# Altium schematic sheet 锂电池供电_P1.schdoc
size 297 x 209 mm; Symbol: Drawing-Symbol_A4; Company: 嘉立创EDA; Version: V1.0; Page Size: A4; @Project Name: 水墨屏demo1; @Update Date: 2026-03-01; @Create Date: 2026-03-01; Device: Drawing-Symbol_A4; @Board Name: Board1; @Page Name: P1; @Create Time: 22:34:30; @Page Count: 1; @Page No: 1; @Schematic Name: Schematic1; @Update Time: 22:34:30; @Assembly Variant: Basic; Border: 1; Title Block Position: 3; Size: A4; Width: 1170; Height: 825; Region Start: 1; X Region Count: 6; Y Region Count: 4; Blade Width: 10
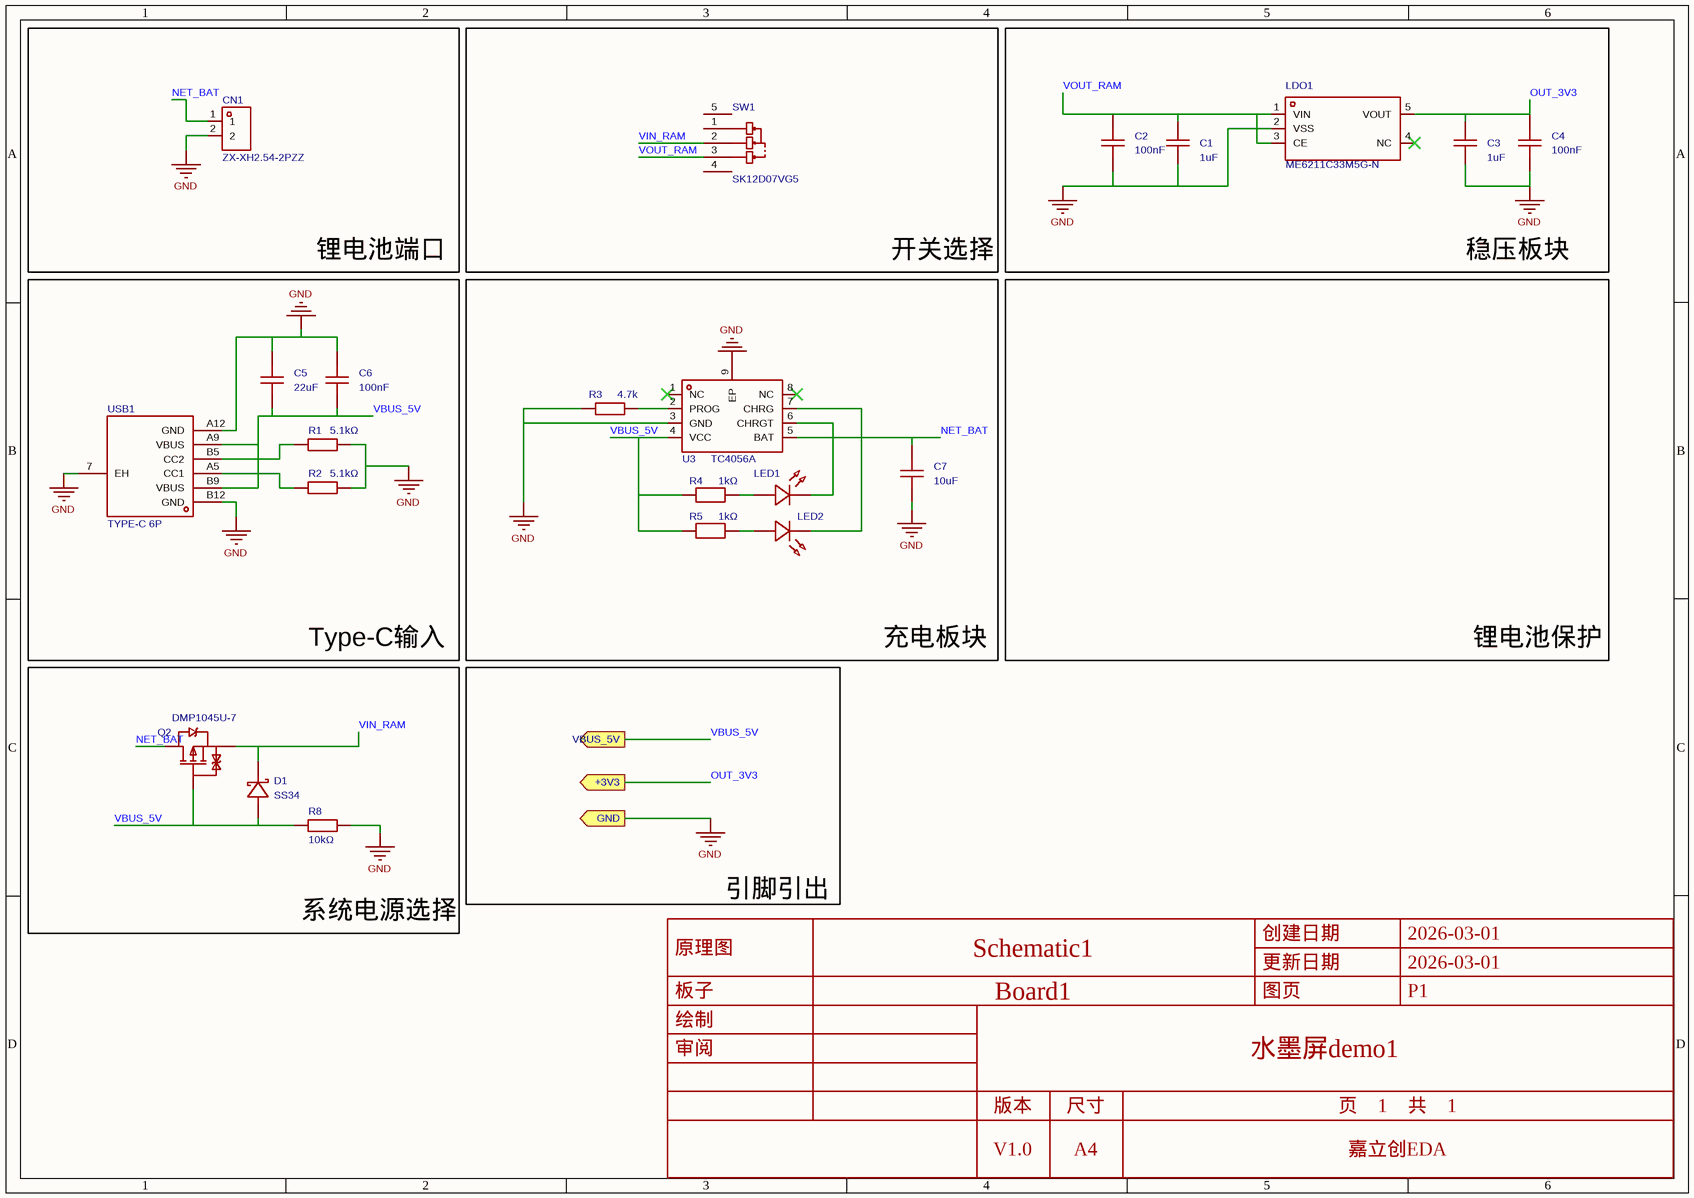
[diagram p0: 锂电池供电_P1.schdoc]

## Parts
C1  1uF  [C0603]
C2  100nF  [C0603]
C3  1uF  [C0603]
C4  100nF  [C0603]
C5  22uF  [C0603]
C6  100nF  [C0603]
C7  10uF  [C0603]
CN1  ZX-XH2.54-2PZZ  [CONN-TH_2P-P2.50_HX25003-2A]
D1  SS34  [SMA_L4.3-W2.6-LS5.0-FD]
LDO1  ME6211C33M5G-N  [SOT-23-5_L3.0-W1.7-P0.95-LS2.8-BL]
LED1  GL0603UR01  [LED0603-FD]  (value not drawn)
LED2  MHT192DUGCT  [LED0603-RD]  (value not drawn)
Q2  DMP1045U-7  [SOT-23-3_L2.9-W1.3-P1.90-LS2.4-BR]
R1  5.1kΩ  [R0603]
R2  5.1kΩ  [R0603]
R3  4.7k  [R0603]
R4  1kΩ  [R0603]
R5  1kΩ  [R0603]
R8  10kΩ  [R0603]
SW1  SK12D07VG5  [SW-TH_SK12D07VG5-1]
U3  TC4056A  [ESOP-8_L4.9-W3.9-P1.27-LS6.0-BL-EP]
USB1  TYPE-C 6P  [TYPE-C-SMD_TYPE-C-6P_1]

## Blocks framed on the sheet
锂电池端口: CN1
开关选择: SW1
稳压板块: C1-C4 LDO1
Type-C输入: C5 C6 R1 R2 USB1
充电板块: C7 LED1 LED2 R3-R5 U3

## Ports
+3V3 (out), GND (out), VBUS_5V (out)

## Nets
GND: C1.1 C2.1 C3.1 C4.1 C5.1 C6.2 C7.1 CN1.2 LDO1.2(VSS) R1.2 R2.2 R3.1 R8.2 U3.3(GND) U3.9(EP) USB1.7(EH) USB1.A12(GND) USB1.B12(GND) ; port GND
NET_BAT: C7.2 CN1.1 Q2.3(D) U3.5(BAT)
OUT_3V3: C3.2 C4.2 LDO1.5(VOUT) ; port +3V3
VBUS_5V: C5.2 C6.1 D1.1(A) Q2.1(G) R4.1 R5.1 R8.1 U3.4(VCC) USB1.A9(VBUS) USB1.B9(VBUS) ; port VBUS_5V
VIN_RAM: D1.2(K) Q2.2(S) SW1.2
VOUT_RAM: C1.2 C2.2 LDO1.1(VIN) LDO1.3(CE) SW1.3
NetLED1_1: LED1.1(A) R4.2
NetLED1_2: LED1.2(C) U3.6(CHRGT)
NetLED2_1: LED2.1(K) U3.7(CHRG)
NetLED2_2: LED2.2(A) R5.2
NetR1_1: R1.1 USB1.B5(CC2)
NetR2_1: R2.1 USB1.A5(CC1)
NetR3_2: R3.2 U3.2(PROG)

Not connected (* = marked no-connect by the designer): LDO1 4(NC)*; SW1 1 4 5; U3 1(NC)* 8(NC)*

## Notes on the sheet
- 锂电池保护
- 系统电源选择
- 引脚引出

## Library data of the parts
C1 C3 = CL10B105KQ8NNNC: 容值:1uF;精度:±10%;额定电压:6.3V;温度系数:X7R;; Manufacturer: SAMSUNG(三星); 3D Model: ac125912035d415993ca9572d50418b10819f05c4eef4c71ace90d822a990e87; 3D Model Transform: 62.992,31.496,0,0,0,0,0,0,0; Tolerance: ±10%; Voltage Rating: 6.3V; Temperature Coefficient: X7R; AddInBom: yes; ModelName: C0603_L1.6-W0.8-H0.8
C2 C4 C6 = CGA0603X7R104K500JT: 容值:100nF;精度:±10%;额定电压:50V;温度系数:X7R;; Manufacturer: HRE(芯声); 3D Model: ac125912035d415993ca9572d50418b1; 3D Model Transform: 62.992,31.496,0,0,0,0,0,0,0; Tolerance: ±10%; Voltage Rating: 50V; Temperature Coefficient: X7R; AddInBom: yes; ModelName: C0603_L1.6-W0.8-H0.8
C5 = 0603X226M6R3NT: 容值:22uF;精度:±20%;额定电压:6.3V;温度系数:X5R;; Manufacturer: FH(风华); 3D Model: ac125912035d415993ca9572d50418b10819f05c4eef4c71ace90d822a990e87; 3D Model Transform: 62.992,31.496,0,0,0,0,0,0,0; Tolerance: ±20%; Voltage Rating: 6.3V; Temperature Coefficient: X5R; AddInBom: yes; ModelName: C0603_L1.6-W0.8-H0.8
C7 = CL10B106MQ8NRNC: 容值:10uF;精度:±20%;额定电压:6.3V;温度系数:X7R;; Manufacturer: SAMSUNG(三星); 3D Model: ac125912035d415993ca9572d50418b10819f05c4eef4c71ace90d822a990e87; 3D Model Transform: 62.992,31.496,0,0,0,0,0,0,0; Tolerance: ±20%; Voltage Rating: 6.3V; Temperature Coefficient: X7R; AddInBom: yes; ModelName: C0603_L1.6-W0.8-H0.8
CN1 = ZX-XH2.54-2PZZ: 插针结构:1x2P;间距:2.5mm;安装方式:直插;参考系列:XH;总PIN数:2P;排数:1;每排PIN数:2;行距:-;额定电流:2A;触头材质:黄铜;触头镀层:锡;工作温度:-25℃~+85℃;; Manufacturer: Megastar(兆星); AddInBom: yes; ModelId: 17c7be61cc0b4bc5acccb67e71c470880819f05c4eef4c71ace90d822a990e87; ModelTransform: 295.275,232.283,0,180,0,0,0,-21.654,-129.921; Pins Structure: 1x2P; Pitch: 2.5mm; Reference Series: XH; Number of PINs Per Row: 2; Current Rating: 2A; Voltage Rating: 250V; Plastic Material: PA66; Flame Retardant Rating: UL94V-0; Z-Height of the Board: 7mm; X-Length of Bottom Edge on Board (Spacing Line): 7.5mm; Y-Width of Bottom Edge on Board: 5.9mm
D1 = SS34_C7420365: 二极管配置:独立式;正向压降(Vf):550mV@3A;直流反向耐压(Vr):40V;整流电流:3A;; Manufacturer: R+O(宏嘉诚); AddInBom: yes; ModelId: 7e24bebe6cd74171ae8c9de6fc5b78aa0819f05c4eef4c71ace90d822a990e87; ModelTransform: 198.4248,103.5431,0,180,0,0,-0.001,0,0; Diode Configuration: 独立式; Voltage - DC Reverse(Vr): 40V; Current - Rectified: 3A; Reverse Leakage Current (Ir): 200uA@40V
LDO1 = ME6211C33M5G-N: 输出类型:固定;工作电压:6V;输出电压:3.3V;输出电流:500mA;电源纹波抑制比(PSRR):70dB@(1kHz);输出极性:正极;; Manufacturer: MICRONE(南京微盟); 3D Model: 0a2a1b8f50944f73965918ad6e5fe1670819f05c4eef4c71ace90d822a990e87; 3D Model Transform: 118.60433,114.173,0,90,0,0,0.0005,0.0005,0; Output Type: 固定; Voltage - Supply: 6V; Output Voltage: 3.3V; Output Current: 500mA; Voltage Dropout: 120mV@(100mA); standby current: 60uA; Noise: 50uVrms; Output Configuration: 正极; Number of Outputs: 1; AddInBom: yes; ModelName: SOT-23-5_L2.9-W1.6-H1.1-LS2.8-P0.95
LED1 = GL0603UR01: 发光颜色:红色;正向压降(Vf):2.4V;正向电流:20mA;波长:620nm~625nm;二极管配置:独立二极管;透镜颜色:无色透明透镜;发光强度:120mcd;发光角度:120°;载带方式:正贴;工作温度:-40℃~+85℃;; Manufacturer: Guiguang light(桂光光电); 3D Model: b57d6965da4c4e30afc1a994a1f136ae0819f05c4eef4c71ace90d822a990e87; 3D Model Transform: 60,30,0,0,0,0,0,0,0; Illumination Color: 红色; Voltage - Forward(Vf): 2.4V; Forward Current: 20mA; Diode Configuration: 独立二极管; Lens Color: 无色透明透镜; Luminous Intensity: 120mcd; Viewing Angle: 120°; AddInBom: yes; ModelName: LED0603_Inf
LED2 = MHT192DUGCT: 发光颜色:翠绿色;正向电压(VF):2.3V~2.8V;正向电流:5mA;主波长:515nm~530nm;透镜颜色:透明透镜;发光强度:285mcd~565mcd;发光角度:120°;工作温度:-40℃~+85℃;; Manufacturer: MEIHUA(美华); 3D Model: 1f0d29a91be547639d425604e9b96ebb0819f05c4eef4c71ace90d822a990e87; 3D Model Transform: 63.7794,32.283,0,0,0,0,0,0,0; Emitted Color: 翠绿色; Forward Current: 5mA; Peak Wavelength: 518nm; Lens Color: 透明透镜; Viewing Angle: 120°; AddInBom: yes
Q2 = DMP1045U-7: 数量:1个P沟道;漏源电压(Vdss):12V;连续漏极电流(Id):5.2A;导通电阻(RDS(on)):31mΩ@4.5V,4A;耗散功率(Pd):1.3W;阈值电压(Vgs(th)):1V@250uA;; Manufacturer: DIODES(美台); AddInBom: yes; ModelId: c62791f0466c4ae2a892c056b845b0ca0819f05c4eef4c71ace90d822a990e87; ModelName: SOT-23-3P_L2.9-W1.3-H1.0-LS2.4-P0.95; ModelTransform: 98.425,114.173,0,180,0,0,0.0005,-0.0005,0; Number: 1个P沟道; Drain to Source Voltage: 12V; Current - Continuous Drain(Id): 5.2A; Pd - Power Dissipation: 1.3W; Gate Charge(Qg): 15.8nC@4.5V; Input Capacitance(Ciss): 1.357nF; Reverse Transfer Capacitance (Crss@Vds): 235pF; Type: P沟道; Output Capacitance(Coss): 504pF
R1 R2 = 0603WAF5101T5E: 电阻类型:厚膜电阻;阻值:5.1kΩ;精度:±1%;功率:100mW;工作电压:75V;温度系数:±100ppm/℃;; Manufacturer: UNI-ROYAL(厚声); 3D Model: fc143cca1e79419f9cd78b61e9279f080819f05c4eef4c71ace90d822a990e87; 3D Model Transform: 31.8897,63.7794,0,90,0,0,0,0,0; Tolerance: ±1%; Power(Watts): 100mW; Voltage-Supply(Max): 75V; AddInBom: yes
R3 = 0603WAF1201T5E: 电阻类型:厚膜电阻;阻值:1.2kΩ;精度:±1%;功率:100mW;工作电压:75V;温度系数:±100ppm/℃;; Manufacturer: UNI-ROYAL(厚声); 3D Model: fc143cca1e79419f9cd78b61e9279f080819f05c4eef4c71ace90d822a990e87; 3D Model Transform: 31.8897,63.7794,0,90,0,0,0,0,0; Tolerance: ±1%; Power(Watts): 100mW; Voltage-Supply(Max): 75V; AddInBom: yes
R4 R5 = FRC0603F1001TS: 电阻类型:厚膜电阻;阻值:1kΩ;精度:±1%;功率:100mW;工作电压:75V;温度系数:±100ppm/℃;; Manufacturer: FOJAN(富捷); 3D Model: fc143cca1e79419f9cd78b61e9279f080819f05c4eef4c71ace90d822a990e87; 3D Model Transform: 31.8897,63.7794,0,90,0,0,0,0,0; Tolerance: ±1%; Power(Watts): 100mW; Voltage-Supply(Max): 75V; AddInBom: yes
R8 = RC0603FR-0710KL: 电阻类型:厚膜电阻;阻值:10kΩ;精度:±1%;功率:100mW;最大工作电压:75V;温度系数:±100ppm/℃;; Manufacturer: YAGEO(国巨); AddInBom: yes; ModelId: fc143cca1e79419f9cd78b61e9279f080819f05c4eef4c71ace90d822a990e87; ModelTransform: 31.8897,63.7794,0,90,0,0,0,0,0; Tolerance: ±1%; Power(Watts): 100mW; Overload Voltage (Max): 75V
SW1 = SK12D07VG5: 电路结构:单刀双掷;安装方式:-;开关颜色:-;额定电流:500mA;额定电压:50V;工作寿命:5千次;; Manufacturer: SHOU HAN(首韩); AddInBom: yes; ModelId: a20b3f2c832c478b84cbf2f4877fc4500819f05c4eef4c71ace90d822a990e87; ModelTransform: 342.9127,370.078,0,0,0,0,0,-98.425,-102.362; Circuit: 单刀双掷; Switch Height: 4.7mm; Current Rating: 500mA; Voltage Rating: 50V; Life: 5千次
U3 = TC4056A.: Manufacturer: FM(富满); 3D Model: d3e00daa36c445139c055a3b9efb85d20819f05c4eef4c71ace90d822a990e87; 3D Model Transform: 240.157,192.913,0,90,0,0,0,0,0; AddInBom: yes; ModelName: ESOP-8_L4.9-W3.9-H1.6-LS6.0-P1.27
USB1 = TYPE-C 6P: 连接器类型:Type-C;协议标准:-;公母:母;安装方式:卧贴;触点数量:6P;端口数量:1;额定电流 - 电源:3A;工作温度:-40℃~+85℃;; Manufacturer: SHOU HAN(首韩); Gender: 母; Number of Ports: 1; Current Rating-Power: 3A; Voltage Rating: 5V; Connect-Disconnect Life: 3千次; Detection color: 黑色; AddInBom: yes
